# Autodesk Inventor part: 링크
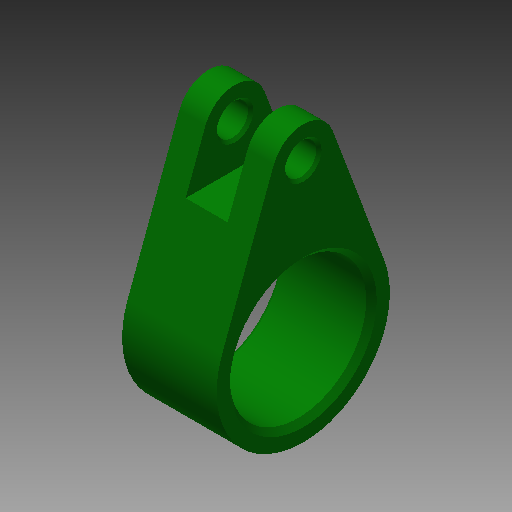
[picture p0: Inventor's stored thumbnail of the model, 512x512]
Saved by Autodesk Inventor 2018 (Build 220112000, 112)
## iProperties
Created: 2016-08
Part Number: 링크
Material: 강철, 탄소
Document SubType Name: Modeling
Designer: mduedu
Density: 7.87 g/cm^3
Appearance: 진녹색
Author: mduedu
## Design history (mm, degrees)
sketch "스케치1"
  geometry: L1 (32.1, 5.62)-(5.775, 15.456); L2 (32.1, -5.62)-(5.775, -15.456); C1 r 13 at (0, 0); C2 r 3 at (30, 0); A1 r 16.5 centre (0, 0) between (5.775, 15.456) and (5.775, -15.456); A2 r 6 centre (30, 0) between (32.1, 5.62) and (32.1, -5.62); 1 further point
  constraints: 4 centre point, 4 end point, 4 point on circle, 4 tangent, 3 coincident, 1 horizontal alignment
  dimensions: "d0" = 33 diameter of A1; "d2" = 12 diameter of A2; "d3" = 30 distance of A2.centre point (0, 0); "d4" = 26 diameter of C1; "d5" = 6 diameter of C2
extrude "돌출1" new body sketch "스케치1" stored distance "d6" = 18; taper "d7" = 0 deg
sketch "스케치2"
  geometry: L1 (-9, 36)-(9, 36) reference; L2 (0, 0)-(0, 36); L3 (-4, 36)-(4, 36); L4 (4, 36)-(4, 22); L5 (4, 22)-(-4, 22); L6 (-4, 22)-(-4, 36)
  constraints: 10 end point, 2 midpoint, 2 parallel, 1 horizontal, 1 perpendicular, 1 point on line
  dimensions: "d8" = 8 distance between parallel lines of L4 L6; "d10" = 14 distance of L3.end L4.end
extrude "돌출2" cut sketch "스케치2" extent not by distance; stored distance "d11" = 20; taper "d12" = 0 deg
chamfer "모따기1" distance "d13" = 1; stored, may be unused: second distance "d14" = 2, angle "d15" = 45 deg
chamfer "모따기2" distance "d16" = 0.5; stored, may be unused: second distance "d17" = 2, angle "d18" = 45 deg
node "솔리드1"
